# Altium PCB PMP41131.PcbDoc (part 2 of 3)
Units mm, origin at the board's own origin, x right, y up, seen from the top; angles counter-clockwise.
Board outline 53.98 x 39 mm, 6 copper layers (Top Layer, Signal Layer 1, Signal Layer 2, Signal Layer 3, Signal Layer 4, Bottom Layer), stack 1.835 mm thick; 91 components, 60 nets, 285 pads, 252 vias.
Unrouted connection lines stored in the file: 18.
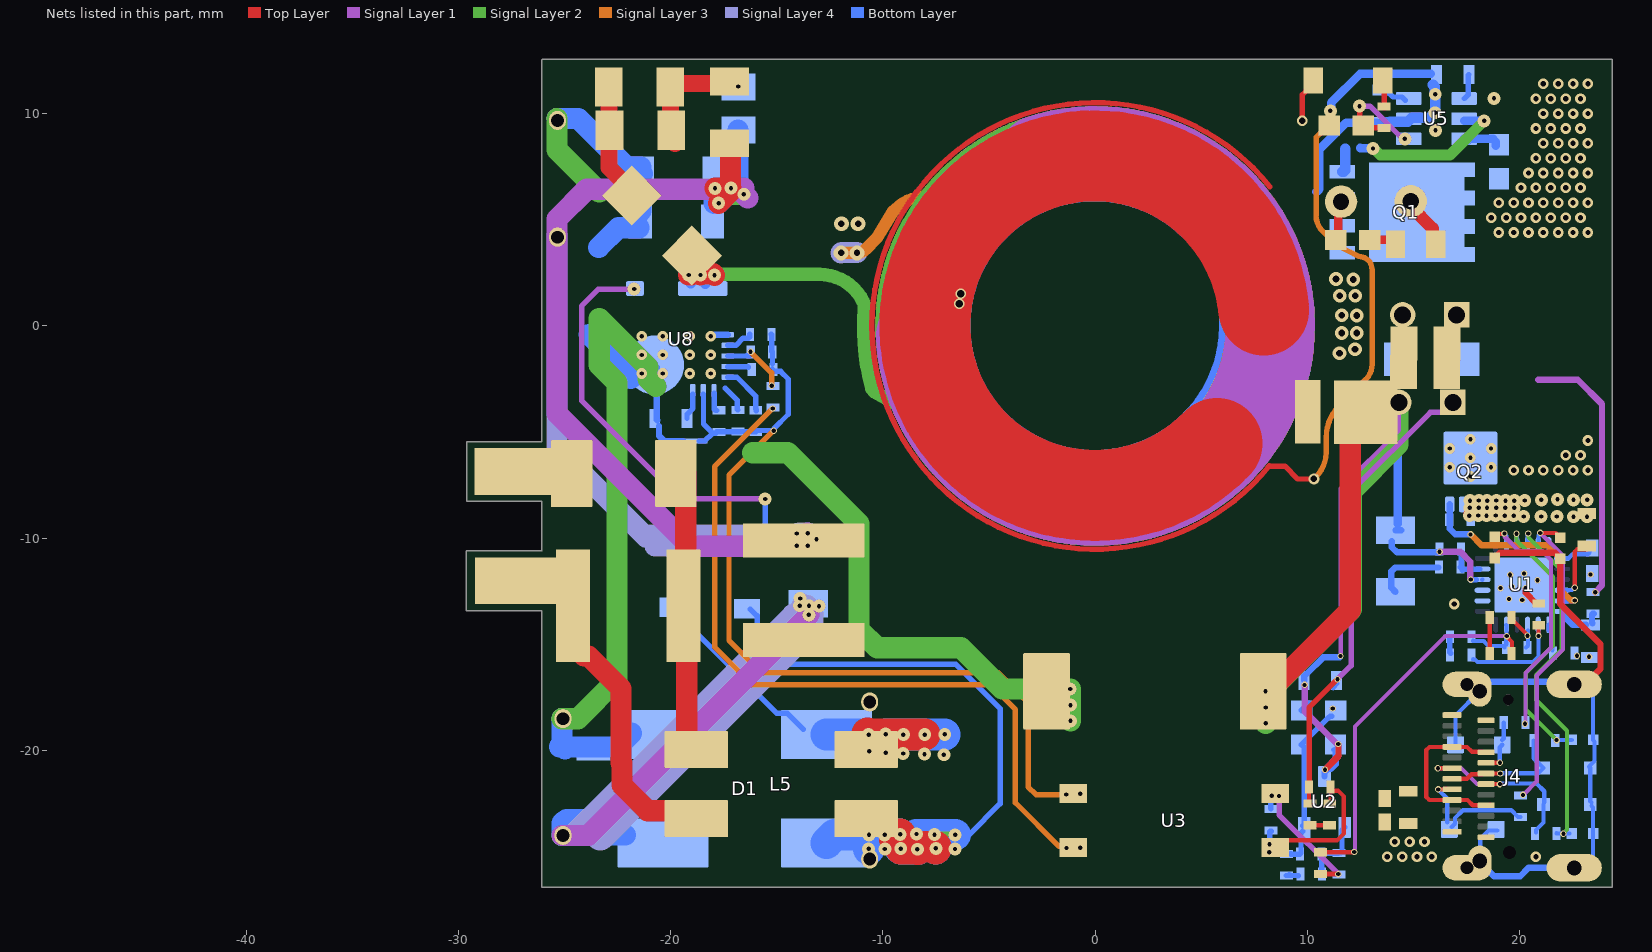
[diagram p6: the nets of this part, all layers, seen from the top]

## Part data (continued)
F1: library part CMP-0124957-1, "50A SMD Fuse 4A 250V 250V SMD Disposable fuses ROHS", Fuse Current=4A, Manufacturer="Shenzhen JDT Fuse", Operating Temperature Range="-55°C to +125°C"
J4: library part CMP-0085712-2, "Receptacle, USB 3.1 Type C, R/A, Gold, SMT", Color=Black, Current_A=1.25A, Manufacturer="JAE Electronics", Voltage_V=20V
L1: library part CMP-0060059-2, "Inductor, Wirewound, Ferrite, 68 uH, 0.9 A, 0.33 ohm, SMD", Manufacturer="Mag Layers", Value1="0.33 ohm", Value2=0.9A, ValueDisplayed=68uH
L5: library part CMP-0124709-1, "Wire Wound Common Mode Choke 1000Ohm @ 100MHz, 4A IDC, 9.0x7.0x4.8mm SMT", Impedance At Frequency="1000Ω @ 100MHz", Manufacturer=MAG-AGA, Operating Temperature Range=to
NT1: library part CMP-0078142-6, "Single point connection between nets.", Manufacturer=N/A
Q1: library part CMP-0001046-2, "MOSFET, N-CH, 150 V, 87 A, PG-TDSON-8", Alternate Manufacturer=None, Manufacturer="Infineon Technologies", Supplier Part Number 1=BSC093N15NS5ATMA1CT-ND, Value2="33 nC"
Q2: library part CMP-0000587-1, "MOSFET, N-CH, 30 V, 60 A, DQG0008A (VSON-CLIP-8)", Alternate Manufacturer=None, Manufacturer="Texas Instruments", Supplier Part Number 1=296-39994-1-ND, Value1=0.003, Value2="23 nC"
R1: library part CMP-0020554-3, "RES, 470 k, 5%, 0.125 W, AEC-Q200 Grade 0, 0805", Manufacturer=Vishay-Dale, Power_W=125mW, Supplier Part Number 1=541-470KACT-ND, TempCo="200 ppm/C", Tolerance_%=5%, Value2=0.125W, Value_Code=470k
R2 R4 R12: library part CMP-0026133-1, "RES, 1.10, 1%, 0.063 W, 0402", Manufacturer=Vishay-Dale, Power_W=63mW, Supplier Part Number 1=541-1.10LLCT-ND, TempCo="100 ppm/C", Tolerance_%=1%, Value2=0.063W, Value_Code=1R10, ValueDisplayed=1.10
R3 R17: library part CMP-0018196-2, "RES, 30.0, 1%, 0.25 W, 1206", Manufacturer="Yageo America", Power_W=250mW, Supplier Part Number 1=311-30.0FRCT-ND, TempCo="100 ppm/C", Tolerance_%=1%, Value2=0.25W, Value_Code=30R0, ValueDisplayed=30.0
R5: library part CMP-0018689-2, "RES, 4.7 k, 5%, 0.25 W, 1206", Manufacturer=Vishay-Dale, Power_W=250mW, Supplier Part Number 1=541-4.7KECT-ND, TempCo="200 ppm/C", Tolerance_%=5%, Value2=0.25W, Value_Code=4k70, ValueDisplayed=4.7k
R7: library part CMP-0026556-2, "RES, 7.68 k, 1%, 0.063 W, AEC-Q200 Grade 0, 0402", Manufacturer=Vishay-Dale, Power_W=63mW, Supplier Part Number 1=541-7.68KLCT-ND, TempCo="100 ppm/C", Tolerance_%=1%, Value2=0.063W, Value_Code=7k68, ValueDisplayed=7.68k
R8: library part CMP-0026220-2, "RES, 28.7 k, 1%, 0.063 W, AEC-Q200 Grade 0, 0402", Manufacturer=Vishay-Dale, Power_W=63mW, Supplier Part Number 1=541-28.7KLCT-ND, TempCo="100 ppm/C", Tolerance_%=1%, Value2=0.063W, Value_Code=28k7, ValueDisplayed=28.7k
R9: library part CMP-0026898-1, "RES, 2.2, 5%, 0.063 W, 0402", Manufacturer=Vishay-Dale, Power_W=63mW, Supplier Part Number 1=541-2.2JCT-ND, TempCo="200 ppm/C", Tolerance_%=5%, Value2=0.063W, Value_Code=2R20, ValueDisplayed=2.2
R10: library part CMP-0026329-2, "RES, 3.01 k, 1%, 0.063 W, AEC-Q200 Grade 0, 0402", Manufacturer=Vishay-Dale, Power_W=63mW, Supplier Part Number 1=541-3.01KLCT-ND, TempCo="100 ppm/C", Tolerance_%=1%, Value2=0.063W, Value_Code=3k01, ValueDisplayed=3.01k
R11: library part CMP-0023550-2, "RES, 43.0 k, 0.1%, 0.1 W, 0603", Manufacturer="Susumu Co Ltd", Power_W=100mW, Supplier Part Number 1=RG16P43.0KBCT-ND, TempCo="25 ppm/C", Tolerance_%=0.1%, Value2=0.1W, Value_Code=43k0, ValueDisplayed=43.0k
R13: library part CMP-0026022-3, "RES, 150, 1%, 0.063 W, AEC-Q200 Grade 0, 0402", Manufacturer=Vishay-Dale, Power_W=63mW, Supplier Part Number 1=541-150LCT-ND, TempCo="100 ppm/C", Tolerance_%=1%, Value2=0.063W, Value_Code=150R, ValueDisplayed=150
R14: library part CMP-0026027-3, "RES, 15.0 k, 1%, 0.063 W, AEC-Q200 Grade 0, 0402", Manufacturer=Vishay-Dale, Power_W=63mW, Supplier Part Number 1=541-15.0KLCT-ND, TempCo="100 ppm/C", Tolerance_%=1%, Value2=0.063W, Value_Code=15k0, ValueDisplayed=15.0k
R15: library part CMP-0026739-1, "RES, 4.70 k, 1%, 0.0625 W, 0402", Manufacturer="Yageo America", Power_W=62.5mW, Supplier Part Number 1=311-4.7KLRCT-ND, TempCo="100 ppm/C", Tolerance_%=1%, Value2=0.0625W, Value_Code=4k70, ValueDisplayed=4.70k
R18: library part CMP-0026866-2, "RES, 1.0, 5%, 0.063 W, 0402", Manufacturer=Vishay-Dale, Power_W=63mW, Supplier Part Number 1=541-1.0JCT-ND, TempCo="200 ppm/C", Tolerance_%=5%, Value2=0.063W, Value_Code=1R00, ValueDisplayed=1.0
R19: library part CMP-0023520-3, "RES, 33.0 k, 0.1%, 0.1 W, 0603", Manufacturer="Susumu Co Ltd", Power_W=100mW, Supplier Part Number 1=RG16P33.0KBCT-ND, TempCo="25 ppm/C", Tolerance_%=0.1%, Value2=0.1W, Value_Code=33k0, ValueDisplayed=33.0k
R21: library part CMP-0026725-1, "RES, 1.00 k, 1%, 0.0625 W, 0402", Manufacturer="Yageo America", Power_W=62.5mW, Supplier Part Number 1=311-1.00KLRCT-ND, TempCo="100 ppm/C", Tolerance_%=1%, Value2=0.0625W, Value_Code=1k00, ValueDisplayed=1.00k
R22: library part CMP-0078497-1, "RES, 0.005, 1%, 1 W, 1206", Manufacturer=Riedon, Power_W=1W, Supplier Part Number 1=696-1372-1-ND, TempCo="50 ppm/C", Tolerance_%=1%, Value_Code=5L000, ValueDisplayed=0.005
R23 R29: library part CMP-0026695-1, "RES, 3.30 k, 1%, 0.1 W, AEC-Q200 Grade 0, 0402", Manufacturer=Panasonic, Power_W=100mW, Supplier Part Number 1=P3.30KLCT-ND, TempCo="100 ppm/C", Tolerance_%=1%, Value2=0.1W, Value_Code=3k30, ValueDisplayed=3.30k
R24 R25 R27 R28: library part CMP-0026970-1, "RES, 6.8, 5%, 0.063 W, 0402", Manufacturer=Vishay-Dale, Power_W=63mW, Supplier Part Number 1=541-6.8JCT-ND, TempCo="200 ppm/C", Tolerance_%=5%, Value2=0.063W, Value_Code=6R80, ValueDisplayed=6.8
R26: library part CMP-0026945-1, "RES, 51 k, 5%, 0.063 W, 0402", Manufacturer=Vishay-Dale, Power_W=63mW, Supplier Part Number 1=541-51KJCT-ND, TempCo="200 ppm/C", Tolerance_%=5%, Value2=0.063W, Value_Code=51k0, ValueDisplayed=51k
R30: library part CMP-0026716-1, "RES, 1.00 k, 1%, 0.063 W, 0402", Manufacturer=Rohm, Power_W=63mW, Supplier Part Number 1=RHM1.00KLCT-ND, TempCo="100 ppm/C", Tolerance_%=1%, Value2=0.063W, Value_Code=1k00, ValueDisplayed=1.00k
R32: library part CMP-0023013-5, "RES, 300, 1%, 0.1 W, 0603", Manufacturer=Yageo, Power_W=100mW, Supplier Part Number 1=311-300HRCT-ND, TempCo="100 ppm/C", Tolerance_%=1%, Value2=0.1W, Value_Code=300R, ValueDisplayed=300
R34: library part CMP-0022438-1, "RES, 47.0 k, 1%, 0.1 W, AEC-Q200 Grade 0, 0603", Manufacturer=Vishay-Dale, Power_W=100mW, Supplier Part Number 1=541-47.0KHCT-ND, TempCo="100 ppm/C", Tolerance_%=1%, Value2=0.1W, Value_Code=47k0, ValueDisplayed=47.0k
R35: library part CMP-0026721-1, "RES, 100 k, 1%, 0.0625 W, 0402", Manufacturer="Yageo America", Power_W=62.5mW, Supplier Part Number 1=311-100KLRCT-ND, TempCo="100 ppm/C", Tolerance_%=1%, Value2=0.0625W, Value_Code=100k
R36: library part CMP-0084244-1, "RES, 1.0 k, 5%, 0.25 W, AEC-Q200 Grade 0, 0603", Manufacturer=Rohm, Power_W=250mW, TempCo="200 ppm/C", Tolerance_%=5%, Value2=0.25W, Value_Code=1k00, ValueDisplayed=1.0k
R42: library part CMP-0025977-1, "RES, 11.5 k, 1%, 0.063 W, 0402", Manufacturer=Vishay-Dale, Power_W=63mW, Supplier Part Number 1=541-11.5KLCT-ND, TempCo="100 ppm/C", Tolerance_%=1%, Value2=0.063W, Value_Code=11k5, ValueDisplayed=11.5k
R43: library part CMP-0026464-2, "RES, 5.23 k, 1%, 0.063 W, AEC-Q200 Grade 0, 0402", Manufacturer=Vishay-Dale, Power_W=63mW, Supplier Part Number 1=541-5.23KLCT-ND, TempCo="100 ppm/C", Tolerance_%=1%, Value2=0.063W, Value_Code=5k23, ValueDisplayed=5.23k
R50: library part CMP-0025712-2, "RES, 12, 5%, 0.1 W, 0603", Manufacturer=Vishay-Dale, Power_W=100mW, Supplier Part Number 1=541-12GCT-ND, TempCo="200 ppm/C", Tolerance_%=5%, Value2=0.1W, Value_Code=12R0, ValueDisplayed=12
RT1: library part CMP-0002353-2, "Thermistor NTC, 100k ohm, 1%, 0402", Manufacturer=MuRata, Power_W=100mW, Tolerance_%=1%
U1: library part CMP-0124680-1, "Integrate multiple protocols, fast charging protocol IC for USBC port", Manufacturer=Injoinic, Max Supply Voltage=25V, Min Supply Voltage=3V, Operating Temperature Range="-40°C to +85°C", Part Number=IP2723TH
U2: library part CMP-0066199-1, "2.5V Low Iq Adjustable Precision Shunt Regulator, DBZ0003A (SOT-23-3)", Alternate Manufacturer="Texas Instruments"
U3: library part CMP-0006160-3, "Optocoupler, 5 kV, 63-125% CTR, SMT", Manufacturer=Vishay-Semiconductor, Supplier Part Number 1=VOL618A-2TCT-ND, Voltage_Isolation_Vrms=5kV
U5: library part CMP-0086802-1, "FAST TURN-OFF INTELLIGENT RECTIF", Manufacturer="Monolithic Power Systems"
U8: library part CMP-0121635-2, Manufacturer="Texas Instruments", Operating Temperature Range=to, PartNumber=UCG28826

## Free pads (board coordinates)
  rect 4x2.2 smd: 5(-27.23,-6.86) 5(-27.22,-12.01)
  rect 1.2x3 smd: 9(10.01,-4.04)
  rect 3x3 smd: 9(12.74,-4.07)
  round 1.524 hole 0.762: 10(11.58,5.85) 10(14.86,5.87)

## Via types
v1: diameter 0.61, hole 0.203, Top Layer to Bottom Layer, tented both sides, 89 vias
v2: diameter 0.5, hole 0.25, Top Layer to Bottom Layer, 75 vias
v3: diameter 0.3, hole 0.2, Top Layer to Bottom Layer, tented both sides, 49 vias
v4: diameter 0.5, hole 0.2, Top Layer to Bottom Layer, tented both sides, 13 vias
v5: diameter 0.65, hole 0.32, Top Layer to Bottom Layer, 10 vias
v6: diameter 0.5, hole 0.2, Top Layer to Bottom Layer, 6 vias
v7: diameter 0.508, hole 0.305, Top Layer to Bottom Layer, 4 vias
v8: diameter 0.7, hole 0.3, Signal Layer 1 to Signal Layer 4, tented both sides, 4 vias
v9: diameter 0.5, hole 0.35, Signal Layer 2 to Signal Layer 3, tented both sides, 2 vias

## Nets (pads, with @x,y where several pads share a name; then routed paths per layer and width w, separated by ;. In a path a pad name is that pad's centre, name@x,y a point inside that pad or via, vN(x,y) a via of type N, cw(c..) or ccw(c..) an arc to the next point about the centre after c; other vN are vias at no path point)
APGND: C16.2 NT1.2 R7.1 R8.1 R42.1 R43.1 RT1.1 U3.3 U8.10 | length 43.3
  Signal Layer 3 w0.254: v3@-15.162,-4.94 -15.178,-4.956 -15.186,-4.956 -17.25,-7.02 -17.25,-14.82 -15.731,-16.339 -4.561,-16.339 -3.16,-17.74 -3.16,-21.71 -2.79,-22.08 -1.38,-22.08 -1.355,-22.055 -0.725,-22.055 v1(-0.71,-22.04)
  Bottom Layer w0.254: NT1.2@-18.648,-5.42 -18.394,-5.42 -18.036,-5.062 R7.1@-17.872,-5.062 ; U8.10@-18.458,-3.213 -18.458,-3.261 -18.45,-3.269 -18.45,-4.62 -18.06,-5.01 ; R7.1@-17.83,-4.998 -17.825,-4.993 R42.1@-16.037,-4.993 ; R42.1@-15.99,-4.988 -15.927,-4.924 -15.134,-4.924 v3(-15.142,-4.933) ; RT1.1@-15.252,-0.4 -15.232,-0.42 -15.232,-1.2 C16.2@-15.212,-1.22 ; R43.1@-15.222,-2.03 -15.222,-2.079 -15.159,-2.142 -14.818,-2.142 -14.46,-2.5 -14.46,-4.16 -15.133,-4.833 v3@-15.133,-4.924 ; R43.1@-15.2,-1.79 C16.2@-15.2,-1.232
  other v1: -1.37,-22.07
CC1: D6.2 J4.A5 R25.2 | length 6
  Top Layer w0.2: v3(16.15,-21.83) 16.49,-21.83 J4.A5@16.52,-21.8
  Bottom Layer w0.2: v3(16.15,-21.83) 16.58,-22.26 D6.2@16.58,-23.38 ; D6.2@16.79,-23.6 16.947,-23.443 16.947,-23.183 17.32,-22.81 19.598,-22.81 19.916,-23.128 R25.2@20.03,-23.128
CC2: D8.2 J4.B5 R28.2 | length 2.2
  Top Layer w0.2: J4.B5@18.6,-20.55 18.63,-20.58 v3(19.06,-20.58)
  Bottom Layer w0.2: v3@19.05,-20.57 19.05,-19.85 D8.2@19.17,-19.73 ; D8.2@19.16,-19.51 D8.2@19.195,-19.475 ; D8.2@19.19,-19.47 19.202,-19.47 19.242,-19.43 R28.2@19.242,-18.69
DN: D2.2 J4.A7 J4.B7 R24.2 | length 8.8
  Top Layer w0.2: v3(16.14,-20.84) 16.145,-20.835 16.805,-20.835 J4.A7@16.81,-20.83 ; J4.B7@18.41,-21.58 v3(19.06,-21.58)
  Signal Layer 1 w0.2: v3(16.14,-20.84) 16.15,-20.83 17.23,-20.83 17.98,-21.58 v3(19.06,-21.58)
  Bottom Layer w0.2: v3(19.06,-21.58) 19.079,-21.561 19.15,-21.561 19.161,-21.55 20.78,-21.55 21.15,-21.92 D2.2@21.15,-22.44 ; R24.2@20.76,-23.86 20.76,-23.738 21.11,-23.388 D2.2@21.11,-22.54
DN1: C28.2 R24.1 U1.16 | length 17.1
  Signal Layer 2 w0.2: v3(20.39,-9.78) 20.409,-9.799 20.409,-9.959 20.86,-10.41 21.97,-11.52 21.97,-15.25 20.77,-16.45 20.77,-17.62 22.22,-19.07 22.22,-23.723 22.05,-23.893 v3(22.05,-23.92)
  Bottom Layer w0.2: U1.16@20.364,-10.324 20.372,-10.317 20.372,-9.798 v3(20.39,-9.78) ; R24.1@21.728,-23.9 21.738,-23.91 C28.2@22.34,-23.91
DP: D7.2 J4.A6 J4.B6 R27.2 | length 5.8
  Top Layer w0.2: J4.A6@16.81,-21.33 17.51,-21.33 17.725,-21.115 18.195,-21.115 J4.B6@18.22,-21.09 ; J4.B6@18.41,-21.08 v3(19.07,-21.08)
  Bottom Layer w0.2: v3@19.08,-21.07 20.86,-21.07 D7.2@21.11,-20.82 20.652,-20.362 R27.2@20.652,-19.53
DP1: C29.2 R27.1 U1.15 | length 12.9
  Signal Layer 2 w0.2: v3(19.84,-9.79) 19.84,-10.1 21.55,-11.81 21.55,-15.08 20.28,-16.35 20.28,-18.06 v3(21.73,-19.51)
  Bottom Layer w0.2: v3(19.84,-9.79) 19.857,-9.807 19.857,-10.317 U1.15@19.864,-10.324 ; R27.1@21.668,-19.53 21.698,-19.5 R27.1@21.72,-19.5 ; v3(21.73,-19.51) R27.1@21.72,-19.5 ; C29.2@22.44,-19.5 R27.1@21.72,-19.5
FB_ACDC: C12.1 C14.2 C23.2 R18.1 U1.5 | length 19.8
  Top Layer w0.2: R18.1@10.6,-24.792 10.606,-24.786 12.194,-24.786 v3(12.2,-24.78) ; v3(19.38,-14.61) 19.38,-14.637 19.63,-14.887 19.63,-15.28 C23.2@19.62,-15.29
  Signal Layer 1 w0.2: v3(12.2,-24.78) 12.219,-24.761 12.219,-24.69 12.23,-24.679 12.23,-18.87 16.49,-14.61 v3(19.38,-14.61)
  Bottom Layer w0.2: C14.2@17.79,-14.826 17.808,-14.845 18.295,-14.845 18.53,-15.08 19.202,-15.08 C12.1@19.272,-15.15 ; C12.1@19.33,-15.03 19.361,-14.999 19.361,-14.629 v3(19.38,-14.61) 19.372,-14.602 19.372,-14.092 U1.5@19.362,-14.082
HVC: C5.1 R4.2 U5.1 | length 4.8
  Top Layer w0.254: v1(12.45,10.35) 12.45,9.52 12.64,9.33 R4.2@13.602,9.33
  Signal Layer 1 w0.254: v1(12.45,10.35) 12.94,10.35 14.412,8.878 14.512,8.878 v1(14.58,8.81)
LINE: F1.1 pad.5@-27.23,-6.86 | length 2.8
  Top Layer w1: pad.5@-27.23,-6.86 -24.76,-6.87 F1.1@-24.63,-6.74 ; F1.1@-24.54,-6.71 F1.1@-24.44,-6.81
NetC1_1: C1.1 F1.2 L5.1 | length 13.6
  Top Layer w1: F1.2@-19.44,-6.81 -19.29,-6.96 C1.1@-19.29,-13.09 ; C1.1@-19.39,-13.19 -19.235,-13.345 -19.235,-19.904 -18.842,-19.904 L5.1@-18.79,-19.956
NetC2_1: C2.1 C8.1 D1.1 L1.1 R5.1 | length 51.2
  Signal Layer 1 w1: C8.1@-25.12,-24 -23.88,-24 v1(-13.49,-13.61)
  Signal Layer 4 w1: -23.31,-24 -24.65,-24 -14.26,-13.61 v1@-13.62,-13.61
  Signal Layer 4 w1.4: -23.31,-24 -13.49,-14.18 v1(-13.49,-13.61) -13.62,-13.61 -13.62,-13.404 v1@-13.67,-13.354
  Bottom Layer w1: C8.1@-25.12,-24 -25.12,-23.42 -25.05,-23.35 ; -24.91,-23.25 -23.88,-23.25 -23.15,-23.98 D1.1@-22.14,-23.98
  other v1: -13.01,-13.2 -13.92,-13.18 -13.48,-13.18 -13.9,-12.84
NetC3_1: C3.1 R1.1 R3.2 R17.2 | length 5.1
  Top Layer w0.8: R3.2@-19.97,9.28 -20.01,9.32 -20.01,11.11 -20.02,11.12 -20.02,11.17 -19.77,11.42 -17.18,11.42 C3.1@-17.1,11.5 ; R3.2@-19.79,8.59 R3.2@-19.79,8.75
  other v1: -16.81,11.28
NetC7_1: C7.1 D1.3 D4.2 L5.2 | length 16.5
  Top Layer w1.5: L5.2@-9.87,-19.355 L5.2@-9.773,-19.258 ; v1(-8.03,-19.25) -8.98,-19.25 -9.01,-19.28 v1(-9.04,-19.25) -9.06,-19.23 v1(-9.87,-19.23) -10.65,-19.23 v1(-10.67,-19.25) ; v1(-10.67,-19.25) -10.73,-19.19 v1(-10.67,-19.25)
  Bottom Layer w0.254: D4.2@-19.92,-13.257 -19.767,-13.257 -19.437,-13.588 -19.437,-13.813 -15.013,-18.237 -14.513,-18.237 D1.3@-13.75,-19
  Bottom Layer w1.5: D1.3@-12.66,-19.25 v1(-10.67,-19.25) ; v1(-9.87,-19.23) -9.85,-19.25 v1(-9.04,-19.25) -7.83,-19.25 -7.82,-19.24 v1(-7.09,-19.24)
  other v1: -7.13,-20.2 -8.04,-20.17 -9.05,-20.14 -9.87,-20.11 -10.64,-20.04
NetC7_2: C7.2 D1.2 D5.2 L5.4 | length 34.4
  Top Layer w1.5: -9.435,-24.195 v1(-9.19,-23.95) ; v1(-9.16,-24.62) -9.15,-24.61 v1@-8.38,-24.61 ; v1@-8.42,-24.61 -8.42,-24.53 -7.51,-24.53 v1(-7.51,-24.61) ; v1@-8.42,-24.61 v1(-8.38,-24.65)
  Signal Layer 2 w0.254: v1(-9.19,-23.95) v1@-6.6,-23.95
  Bottom Layer w0.254: D5.2@-16.247,-13.347 -16.237,-13.347 -15.927,-13.658 -15.927,-13.797 -15.917,-13.807 -15.917,-14.353 -14.33,-15.94 -6.56,-15.94 -4.48,-18.02 -4.48,-22.5 -5.95,-23.97 v1(-6.6,-23.97)
  Bottom Layer w1.5: D1.2@-12.66,-24.35 -12.28,-23.97 -10.67,-23.97 v1(-10.66,-23.97) ; v1(-10.67,-24.63) -10.66,-24.62 v1(-10.66,-23.97) ; v1@-9.81,-23.97 v1(-9.92,-23.97) v1(-10.66,-23.97) ; v1(-9.19,-23.95) -9.19,-24.59 v1(-9.16,-24.62) v1@-8.41,-24.62 ; v1(-8.38,-24.65) v1@-8.41,-24.62 ; v1(-7.51,-24.61) -7.51,-24.03 v1@-7.57,-23.97 ; v1(-6.6,-23.97) v1@-7.57,-23.97 ; v1@-8.41,-24.62 -8.42,-24.61 -8.42,-23.97 v1@-7.57,-23.97
  other v1: -9.91,-24.64 -6.61,-24.64 -7.57,-23.96 -8.42,-23.93
NetC10_1: C10.1 R9.2 U1.24 | length 1.9
  Bottom Layer w0.3: U1.24@22.175,-13.48 22.175,-13.775 22.48,-14.08 C10.1@23.113,-14.08 ; C10.1@23.42,-14.01 23.4,-13.99 23.4,-13.598 R9.2@23.44,-13.558 R9.2@23.48,-13.558
NetC11_1: C11.1 U1.1 | length 1.3
  Bottom Layer w0.2: U1.1@21.364,-14.076 21.364,-14.336 21.384,-14.356 21.423,-14.356 21.54,-14.473 C11.1@21.54,-15.278
NetC12_2: C12.2 R29.2 U1.3 | length 1.7
  Top Layer w0.2: R29.2@19.65,-13.85 v3@20.34,-14.54
  Bottom Layer w0.2: C12.2@20.288,-15.15 20.378,-15.06 20.378,-14.672 v3@20.39,-14.66 ; v3@20.379,-14.571 U1.3@20.379,-14.351
  other v3: 20.36,-14.59
NetC13_1: C13.1 R50.2 | length 1
  Top Layer w0.4: R50.2@12.93,4.05 13.92,4.05 C13.1@13.95,4.02
NetC14_1: C14.1 R23.1 | length 0.8
  Bottom Layer w0.254: C14.1@16.702,-14.64 16.702,-15.382 R23.1@16.74,-15.42
NetC15_1: C15.1 U8.11 | length 1.3
  Bottom Layer w0.254: C15.1@-19.228,-4.36 -19.228,-4.169 -18.95,-3.891 -18.95,-3.221 U8.11@-18.958,-3.213
NetC16_1: C16.1 R12.1 U8.5 | length 3.2
  Signal Layer 3 w0.254: v3(-16.232,-1.223) -15.24,-2.215 v3@-15.24,-2.79
  Bottom Layer w0.254: U8.5@-17.31,-1.415 -16.44,-1.415 -16.423,-1.398 -16.292,-1.398 -16.228,-1.334 C16.1@-16.228,-1.22
  other v3: -15.242,-2.823
NetC18_2: C18.2 R13.2 | length 0.8
  Top Layer w0.2: C18.2@10.24,-23.58 10.302,-23.518 R13.2@11.03,-23.518
NetC20_1: C20.1 R15.1 | length 0.6
  Bottom Layer w0.254: R15.1@9,-25.888 9.548,-25.888 C20.1@9.56,-25.9 ; R15.1@9.14,-25.84 R15.1@9.144,-25.844
NetC20_2: C20.2 C21.2 R2.1 U2.1 | length 3.1
  Bottom Layer w0.254: C21.2@10.658,-24.87 10.682,-24.846 R2.1@11.454,-24.846 ; C21.2@10.67,-24.918 10.67,-25.742 C20.2@10.728,-25.8 ; R2.1@11.48,-24.822 11.556,-24.822 11.62,-24.759 11.62,-23.75 U2.1@11.75,-23.62
NetC21_1: C21.1 R11.1 R15.2 R19.2 U2.2 | length 7.5
  Bottom Layer w0.254: R15.2@9.2,-24.86 9.23,-24.89 C21.1@9.642,-24.89 ; C21.1@9.642,-24.87 9.69,-24.822 9.69,-23.89 U2.2@9.78,-23.8 ; U2.2@9.78,-23.54 9.85,-23.47 9.85,-19.86 R19.2@9.71,-19.72 10.979,-18.451 cw(c11.15,-18.621) R11.1@11.15,-18.38
  other v3: 11.19,-18.02
NetC23_1: C23.1 R29.1 | length 1.6
  Top Layer w0.2: C23.1@18.582,-15.42 18.582,-13.878 R29.1@18.64,-13.82
NetC24_2: 
NetC26_1: C26.1 R21.1 U1.11 | length 1.4
  Bottom Layer w0.254: R21.1@17.198,-11.36 17.24,-11.318 C26.1@17.24,-10.777 ; R21.1@17.286,-11.516 17.341,-11.46 U1.11@18.11,-11.46
NetC31_1: C31.1 U5.4 | length 1.2
  Bottom Layer w0.254: U5.4@17.37,10.71 17.387,10.71 17.56,10.883 17.56,11.8 C31.1@17.6,11.84
NetD3_1: D3.1 R3.1 R17.1 | length 5.4
  Top Layer w0.8: R17.1@-22.91,11.11 -22.91,9.415 -22.9,9.405 -22.9,7.456 -21.828,6.384 D3.1@-21.828,6.138
NetD4_1: D4.1 D5.1 U8.1 | length 23
  Signal Layer 1 w0.254: v1@-21.7,1.73 -23.4,1.73 -24.19,0.94 -24.19,-3.52 -19.56,-8.15 v1(-15.55,-8.15)
  Bottom Layer w0.254: D4.1@-19.54,-9.912 -16.118,-9.912 D5.1@-16.11,-9.92 ; D5.1@-15.928,-9.72 -15.55,-9.342 v1(-15.55,-8.15)
  other v1: -21.72,1.74
NetD9_1: D9.1 R4.1 | length 1.3
  Top Layer w0.254: D9.1@13.537,11.55 13.62,11.467 R4.1@13.62,10.27
NetQ1_4: Q1.4 U5.5 | length 8.7
  Signal Layer 2 w0.5: v1@13.131,8.339 13.42,8.05 16.71,8.05 v1(18.32,9.66)
  Bottom Layer w0.4: 12.47,8.39 12.49,8.37 13.07,8.37 v1(13.08,8.36) ; U5.5@17.37,9.66 18.26,9.66 v1@18.27,9.67
  Bottom Layer w0.5: Q1.4@11.64,7.26 11.705,7.26 11.78,7.335 11.78,8.33
NetQ2_4: Q2.4 R35.1 U1.23 | length 9.9
  Signal Layer 3 w0.3: v3(17.68,-9.82) 18.19,-10.33 21.29,-10.33 21.92,-10.96 21.92,-12.45 22.39,-12.92 v3@22.59,-12.92
  Bottom Layer w0.254: U1.23@21.99,-12.95 21.997,-12.943 22.565,-12.943 22.59,-12.918 v3@22.59,-12.91
  Bottom Layer w0.3: Q2.4@16.695,-8.403 16.695,-9.555 16.96,-9.82 v3@17.665,-9.82
  other v3: 22.59,-12.93
NetR2_2: R2.2 R14.1 R18.2 U3.2 | length 6.9
  Top Layer w0.254: R18.2@10.64,-25.82 10.646,-25.814 11.444,-25.814 v3(11.45,-25.82)
  Signal Layer 1 w0.254: v3(8.31,-22.13) v3@8.62,-22.13 ; v3(8.66,-22.14) 8.66,-23.03 v3(11.45,-25.82)
  Bottom Layer w0.254: v3@8.26,-22.2 8.26,-22.732 R14.1@8.28,-22.752 ; v3(8.31,-22.13) 8.319,-22.121 8.679,-22.121 v3@8.69,-22.11
NetR7_2: R7.2 U8.9 | length 0.9
  Bottom Layer w0.254: U8.9@-17.95,-3.18 -17.95,-3.919 -17.887,-3.982 R7.2@-17.83,-3.982
NetR8_2: R8.2 U8.8 | length 1.3
  Bottom Layer w0.254: U8.8@-17.423,-2.937 -16.87,-3.49 -16.87,-3.922 R8.2@-16.83,-3.962
NetR10_1: R10.1 R13.1 R14.2 U3.1 | length 7.6
  Top Layer w0.2: U3.1@8.73,-24.41 8.91,-24.23 11.39,-24.23 11.71,-23.91 11.71,-22.17 11.429,-21.889 11.168,-21.889 11.078,-21.798 R10.1@11.078,-21.72 R10.1@11.078,-21.832 ; R13.1@11.03,-22.502 11.078,-22.454 R10.1@11.078,-21.834
  Bottom Layer w0.2: v3(8.2,-24.79) 8.205,-24.785 8.205,-24.425 v3(8.21,-24.42)
  Bottom Layer w0.254: v3(8.21,-24.42) 8.219,-24.411 8.219,-23.831 8.24,-23.81 R14.2@8.3,-23.81
NetR12_2: R12.2 U3.4 | length 36.1
  Signal Layer 3 w0.254: v3(-15.192,-3.893) -17.93,-6.631 -17.93,-15.13 -16.152,-16.908 -4.922,-16.908 -3.76,-18.07 -3.76,-22.46 -1.698,-24.522 -1.418,-24.522 v1(-1.35,-24.59) -1.345,-24.585 -0.705,-24.585 v1(-0.7,-24.58)
NetR23_2: R23.2 R30.2 U1.2 | length 5.2
  Top Layer w0.2: v3@20.89,-14.6 20.88,-14.59 20.88,-14.108 R30.2@20.89,-14.098
  Bottom Layer w0.2: R23.2@17.8,-15.706 17.808,-15.715 17.885,-15.715 18,-15.83 20.63,-15.83 20.88,-15.58 v3(20.88,-14.6) 20.872,-14.592 20.872,-14.089 U1.2@20.867,-14.084
NetR26_2: R26.2 U1.19 | length 1.5
  Bottom Layer w0.2: U1.19@21.99,-10.95 21.998,-10.942 22.298,-10.942 22.49,-10.75 23.21,-10.75 23.28,-10.68 R26.2@23.28,-10.54
NetR32_2: R32.2 U5.6 | length 1.7
  Bottom Layer w0.4: U5.6@17.37,8.81 18.735,8.81 18.86,8.685 R32.2@18.86,8.49 ; U5.6@17.54,8.71 U5.6@17.545,8.715
NetR34_2: R34.2 U5.3 | length 1.3
  Bottom Layer w0.254: R34.2@13.51,11.112 13.701,11.112 14.029,10.783 14.447,10.783 U5.3@14.6,10.63
NetR36_1: R36.1 U1.22 | length 3
  Top Layer w0.2: v3(22.59,-12.33) 22.59,-10.633 22.707,-10.516 23.174,-10.516 R36.1@23.2,-10.49
  Bottom Layer w0.2: U1.22@21.99,-12.45 21.998,-12.442 22.45,-12.442 22.563,-12.33 v3(22.59,-12.33)
NetR42_2: R42.2 U8.7 | length 2.4
  Bottom Layer w0.254: U8.7@-17.31,-2.415 -16.885,-2.415 -16,-3.3 -16,-3.908 -15.96,-3.948 R42.2@-15.96,-3.99
NetR43_2: R43.2 U8.6 | length 1
  Bottom Layer w0.254: U8.6@-17.31,-1.915 -17.308,-1.917 -16.363,-1.917 R43.2@-16.34,-1.94
NetRT1_2: RT1.2 U8.4 | length 1.3
  Bottom Layer w0.254: U8.4@-17.31,-0.915 -17.308,-0.913 -16.923,-0.913 -16.588,-0.578 -16.332,-0.578 -16.268,-0.514 RT1.2@-16.268,-0.4
Neture: C1.2 L5.3 pad.5@-27.22,-12.01 | length 16.2
  Top Layer w1: pad.5@-26.36,-12.03 C1.2@-24.76,-12.03 ; C1.2@-24.72,-12.03 C1.2@-24.42,-12.33 ; C1.2@-24.59,-13.19 -24.59,-15.04 -24.08,-15.55 -23.869,-15.55 -22.333,-17.086 -22.333,-20.59 ; C1.2@-24.37,-13.19 C1.2@-24.37,-12.64 ; -22.29,-20.59 -22.29,-21.629 -21.088,-22.831 -19.165,-22.831 L5.3@-18.79,-23.206
PGND: C2.2 C8.2 C9.2 C15.2 C19.2 C22.2 C32.1 D1.4 NT1.1 U8.3 U8.12 | length 82.9
  Top Layer w0.2: C32.1@-2.294,-17.209 -2.185,-17.1 v1(-1.18,-17.1) ; C32.1@-1.27,-18.5 v1(-1.17,-18.6) C32.1@-1.27,-18.5 ; C32.1@-1.27,-17.96 v1(-1.17,-17.86) C32.1@-1.27,-17.96
  Signal Layer 2 w0.637: -12.986,2.426 cw(c-12.986,0.141) -10.932,1.143 cw(c-11.504,0.864) -10.87,0.809 ccw(c-0.344,-0.097) -10.516,-2.95
  Signal Layer 2 w1: C9.2@-25.35,9.77 -25.35,8.3 -23.36,6.31 ; C8.2@-25.12,-18.5 -24.36,-18.5 -22.52,-16.66 -22.52,-2.68 -23.36,-1.84 -23.36,0.35 -21.063,-1.947 ; -21.063,-2.487 -20.69,-2.86 ; -16.13,-5.97 -14.48,-5.97 -11.13,-9.32 -11.13,-14.3 -10.27,-15.16 -6.32,-15.16 -4.38,-17.1 v1(-1.18,-17.1) ; v1(-1.17,-18.6) v1(-1.17,-17.86) v1@-1.17,-17.11
  Bottom Layer w0.3: U8.12@-20.758,-1.839 -20.655,-1.942 -20.655,-4.425 C15.2@-20.63,-4.45 ; C15.2@-20.55,-4.72 -20.55,-5.17 -20.3,-5.42 NT1.1@-19.41,-5.42 ; v4@-17.94,-0.43 -17.925,-0.415 U8.3@-17.31,-0.415
  Bottom Layer w1: C9.2@-25.35,9.77 -24.35,9.77 -22.05,7.47 C22.2@-21.39,7.47 ; -25.23,-19.82 -25.19,-19.82 -25.12,-19.75 C8.2@-25.12,-18.5 ; -24.98,-19.92 -24.9,-19.84 -22.49,-19.84 D1.4@-21.84,-19.19 ; -23.85,-0.4 -22.414,-1.836 ; -23.39,3.69 -22.46,4.62 C19.2@-21.49,4.62 ; U8.12@-21.873,-2.47 -21.584,-2.181 -21.419,-2.181 v4(-21.36,-2.24) ; U8.12@-21.85,-2.18 U8.12@-21.81,-2.14 ; C19.2@-21.49,5.31 -21.39,5.41 -21.39,7.12 C22.2@-21.34,7.17
  other v4: -20.37,-2.24 -19.1,-2.24 -18.11,-2.24 -21.36,-1.365 -20.37,-1.365 -19.1,-1.365 -18.11,-1.365 -21.36,-0.49 -20.37,-0.49 -19.1,-0.49 -18.11,-0.49
RTN: C27.1 C28.1 C29.1 C30.1 C38.2 D2.1 D6.1 D7.1 D8.1 D13.2 J4.A1 J4.A12 J4.B1 J4.B12 J4.S1 J4.S2 J4.S3 J4.S4 R21.2 R22.2 | length 37.3
  Top Layer w0.3: C30.1@18.72,-11.01 18.74,-11.01 19.06,-10.69 21.664,-10.69 C27.1@21.81,-10.836 ; C27.1@21.9,-10.98 21.9,-13.1 23.8,-15 23.8,-16.15 23.37,-16.58 J4.S4@23.25,-16.58
  Bottom Layer w0.2: D8.1@16.97,-19.73 16.97,-18.35 J4.S2@18.11,-17.21 ; J4.S1@18.13,-25.11 18.13,-24.17 18.53,-23.77 D6.1@18.93,-23.77 ; J4.S4@21.784,-16.51 J4.S4@22.13,-16.51 ; J4.S3@22.82,-25.5 22.937,-25.5 23.45,-24.987 C28.1@23.45,-23.91 23.45,-22.68 D2.1@23.37,-22.6 ; J4.S3@22.86,-25.16 J4.S3@22.91,-25.21 ; J4.S4@22.89,-17.29 23.317,-17.29 23.45,-17.423 C29.1@23.45,-19.5 ; D7.1@23.25,-20.76 23.52,-20.49 C29.1@23.52,-19.59 ; D7.1@23.31,-20.82 23.31,-22.39 D2.1@23.37,-22.45
  Bottom Layer w0.3: R22.2@14.14,-12.53 13.95,-12.34 13.95,-11.556 14.126,-11.38 R21.2@16.162,-11.38 ; J4.S2@17.51,-16.885 18.304,-16.885 18.429,-16.76 22.435,-16.76 J4.S4@22.56,-16.885 ; J4.S1@18.11,-25.25 18.78,-25.92 20.012,-25.92 20.407,-25.525 22.075,-25.525 J4.S3@22.25,-25.7
  other v2: 13.755,-24.999 14.455,-24.999 15.155,-24.999 15.855,-24.999 20.755,-24.999 20.755,-24.999 14.105,-24.299 14.805,-24.299 15.505,-24.299
SGND: C4.2 C6.2 C10.2 C11.2 C17.1 C26.2 C32.2 C49.2 EC6.2 EC7.2 pad.9@12.74,-4.07 R19.1 R22.1 R26.1 R30.1 U1.8 U1.9 U1.10 U1.18 U1.25 U2.3 | length 67
  Top Layer w0.3: v3(10.82,-20.9) 11.46,-20.26 v3@11.46,-19.72 ; v3@20.27,-12.42 20.27,-12.576 20.776,-13.082 R30.1@20.89,-13.082
  Top Layer w1: v1(8.02,-17.21) 8.115,-17.21 8.19,-17.21 12.01,-13.39 pad.9@12.01,-4.69
  Signal Layer 1 w0.2: v3@11.56,-15.56 11.56,-7.66 14.3,-4.92 EC7.2@14.3,-3.6
  Signal Layer 1 w0.3: v3(9.86,-16.91) 9.86,-18.16 v3@11.4,-19.7 ; v3(10.82,-20.9) 11.46,-20.26 v3@11.46,-19.74 ; v3(16.22,-10.64) 17.2,-10.64 17.67,-11.11 v3@17.67,-11.9
  Signal Layer 2 w1: v1@8.01,-17.25 8.02,-17.97 v1(8.03,-18.71) ; v1(8.02,-17.21) 8.2,-17.21 12.06,-13.35 12.06,-7.79 14.262,-5.588 14.262,-3.692 14.344,-3.61 EC7.2@14.37,-3.61
  Bottom Layer w0.2: R19.1@11.215,-19.96 R19.1@11.24,-19.96 ; U1.10@18.231,-11.958 U1.10@18.239,-11.95
  Bottom Layer w0.254: v3(17.69,-11.95) U1.10@17.95,-11.95
  Bottom Layer w0.3: C17.1@9.838,-16.7 9.838,-16.509 9.942,-16.405 10.747,-15.6 v3@11.52,-15.6 ; U2.3@10.8,-21.22 10.8,-21.02 10.95,-20.87 11.095,-20.87 11.32,-20.645 R19.1@11.32,-19.95 ; R22.1@13.97,-10.15 13.97,-10.42 14.21,-10.66 15.996,-10.66 16.001,-10.655 16.205,-10.655 v3(16.22,-10.64) ; R22.1@14.14,-9.63 R22.1@14.415,-9.63
  Bottom Layer w0.4: 14.14,-4.28 14.24,-4.38 R22.1@14.24,-9.32
  other v1: 8.03,-17.97
  other v2: 16.905,-13.099 16.905,-13.099
  other v3: 11.44,-19.69 23.26,-15.58 11.55,-15.55 22.69,-15.53 20.11,-12.91 19.49,-12.86 20.27,-12.36 19.09,-12.35 19.62,-12.28 20.83,-11.98 19.54,-11.72 23.33,-11.71 20.2,-11.66
Vaux: D9.2 | length 1.8
  Top Layer w0.254: v7(9.75,9.66) 9.75,10.885 10.015,11.15 D9.2@10.14,11.15
  Bottom Layer w0.254: v7@9.701,9.611 v7(9.75,9.66)
Vbus: C3.2 C9.1 C19.1 C22.1 L1.2 R1.2 R5.2 | length 677.2
  Top Layer w1: v1(-17.91,6.48) -17.9,6.49 v1(-17.16,6.49) ; v1(-17.74,5.78) -17.16,6.36 v1(-17.16,6.49) ; C3.2@-17.025,8.66 -17.025,8.61 -17.175,8.46 -17.175,6.505 v1(-17.16,6.49)
  Signal Layer 1 w1: C9.1@-25.35,4.208 -25.35,-4.12 -19.41,-10.06 ; C9.1@-25.35,4.27 -25.35,5.04 -23.95,6.44 v1@-17.95,6.44 ; -19.18,-10.38 -14.364,-10.38 -14.344,-10.36 v1(-14.06,-10.36) ; v1(-17.74,5.78) -17.475,6.045 ; v1(-17.16,6.49) v1@-16.55,6.49 ; v1(-16.55,6.2) v1@-16.37,6.02 ; v1@-13.875,-10.175 v1@-13.715,-10.175 ; v1(-13.54,-10.35) v1@-13.715,-10.175 ; v1(-13.54,-9.77) -13.54,-10 v1@-13.715,-10.175
  Signal Layer 1 w4.2: -8.237,-0.462 ccw(c0,0) -2.576,7.838
  Signal Layer 2 w0.505: -18.02,2.5 -17.7,2.5
  Signal Layer 2 w0.637: -10.41,-3.09 -9.4,-3.67 ; -9.817,-2.065 cw(c0,0) -9.298,-3.766 ; -9.7,-2.14 -8.741,-2.743 ; -9.063,-1.19 cw(c0,0) -8.69,-2.837 ; -9.01,-1.25 -8.02,-2.03 ; -8.238,-0.441 cw(c0,0) -7.952,-2.196 ; -8.18,-0.49 -7.27,-1.27 ; -7.35,0.37 cw(c0,0) -7.216,-1.441 ; -7.32,0.3 -6.47,-0.68 ; -6.423,-0.758 ccw(c0,0) v9@-6.395,0.966
  Signal Layer 2 w1: -17.698,6.188 -17.157,6.194 v1(-16.55,6.2)
  Signal Layer 3 w0.58: v8@-11.263,3.44 v8(-11.97,3.44) v8@-11.246,3.457 ; v8(-11.22,3.44) ccw(c-11.22,3.995) -10.828,3.602 -10.3,4.13 -9.51,5.41 ; -9.394,5.496 cw(c-7.96,4.062) -7.96,6.09
  Signal Layer 3 w0.637: -9.016,4.399 ccw(c0,0) -7.952,6.116 ; -8.98,4.49 -7.62,5.17 ; -8.417,3.565 ccw(c0,0) -7.494,5.235 ; -8.39,3.65 -7.1,4.3 ; -7.734,2.872 ccw(c0,0) -7.014,4.344 ; -7.68,2.94 -6.53,3.48 ; -7.062,2.069 ccw(c0,0) -6.447,3.549 ; -7.02,2.18 -5.89,2.77 ; v9@-6.277,1.561 ccw(c0,0) -5.791,2.881
  Signal Layer 4 w1: C9.1@-25.35,4.27 -25.35,-5.75 -21.135,-9.965 ; -21.03,-9.86 -14.06,-9.86 -14.04,-9.86 -13.95,-9.77 v1(-13.54,-9.77) ; -20.73,-10.37 -14.07,-10.37 v1(-14.06,-10.36) -14.04,-10.36 -14.03,-10.35 v1(-13.54,-10.35) ; v8(-11.97,3.44) -11.95,3.46 v8@-11.22,3.46
  Signal Layer 4 w4.2: -8.248,-0.159 ccw(c0,0) -4.919,6.623
  Bottom Layer w1: v1@-17.95,5.78 -17.95,6.44 v1(-17.91,6.48) -17.17,6.48 v1(-17.16,6.49) -16.83,6.82 R1.2@-16.83,9.224
  other v1: -13.13,-10.05 -14.06,-9.78
  other v8: -11.96,4.81 -11.17,4.81
  other v9: -6.41,1.04 -6.33,1.52
VO_ACDC: C4.1 C6.1 C13.2 C17.2 C18.1 C49.1 EC6.1 EC7.1 pad.10@14.86,5.87 Q1.5 Q1.6 Q1.7 Q1.8 Q1.9 Q2.5 Q2.6 Q2.7 Q2.8 Q2.9@17.67,-6.228 R9.1 R10.2 R11.2 R32.1 | length 37.6
  Top Layer w0.2: R10.2@10.062,-21.832 10.062,-22.444 C18.1@10.12,-22.502
  Top Layer w0.254: R10.2@10.01,-21.64 10.075,-21.575 10.075,-17.975 v3(11.41,-16.64)
  Top Layer w0.3: C13.2@16.04,3.85 C13.2@16.04,4.05
  Top Layer w0.6: pad.10@14.86,5.87 14.86,5.62 15.89,4.59 15.89,3.92 C13.2@16.01,3.8
  Signal Layer 1 w0.254: v3(11.41,-16.64) 12.05,-16 12.05,-7.81 15.787,-4.073 16.367,-4.073 16.4,-4.04 EC7.1@16.4,-3.74
  Signal Layer 1 w0.3: 20.87,-2.54 22.73,-2.54 23.87,-3.68 23.87,-12.22 v3(23.55,-12.54)
  Bottom Layer w0.2: C17.2@11.208,-17.062 11.208,-17.044 C17.2@11.413,-16.84
  Bottom Layer w0.3: R11.2@9.73,-18.11 9.735,-18.11 R11.2@10.06,-17.785
  other v2: 19.705,-6.799 20.405,-6.799 21.105,-6.799 21.805,-6.799 22.505,-6.799 23.205,-6.799 22.155,-6.099 22.855,-6.099 23.205,-5.399 19.005,4.401 19.705,4.401 20.405,4.401 21.105,4.401 21.805,4.401 22.505,4.401 23.205,4.401 18.655,5.101 19.355,5.101 20.055,5.101 20.755,5.101 21.455,5.101 22.155,5.101 22.855,5.101 19.005,5.801 19.705,5.801 20.405,5.801 21.105,5.801 21.805,5.801 22.505,5.801 23.205,5.801 20.055,6.501 20.755,6.501 21.455,6.501 22.155,6.501 22.855,6.501 20.405,7.201 21.105,7.201 21.805,7.201 22.505,7.201 23.205,7.201 20.755,7.901 21.455,7.901 22.155,7.901 22.855,7.901 21.105,8.601 21.805,8.601 22.505,8.601 23.205,8.601 20.755,9.301 21.455,9.301 22.155,9.301 22.855,9.301 21.105,10.001 21.805,10.001 22.505,10.001 23.205,10.001 20.755,10.701 21.455,10.701 22.155,10.701 22.855,10.701 21.105,11.401 21.805,11.401 22.505,11.401 23.205,11.401
  other v4: 17.67,-5.338
  other v6: 17.67,-7.09 16.695,-6.652 18.645,-6.652 17.67,-6.214 16.695,-5.776 18.645,-5.776
VOUT_C: C38.1 D13.1 J4.A4 J4.A9 J4.B4 J4.B9 Q2.1 Q2.2 Q2.3 R35.2 R36.2 | length 8.7
  Top Layer w0.2: J4.A4@16.56,-22.32 16.55,-22.33 15.737,-22.33 15.59,-22.183 15.59,-19.98 15.74,-19.83 J4.A9@16.81,-19.83 17.51,-19.83 17.74,-20.06 J4.B4@18.23,-20.06 ; J4.A4@16.81,-22.33 17.53,-22.33 17.78,-22.58 J4.B9@18.41,-22.58 ; v1@17.45,-8.8 v1@17.77,-8.8 ; v1@18.362,-8.789 18.659,-8.789 v1@18.66,-8.79 ; J4.B9@18.61,-22.55 J4.B9@18.64,-22.58 ; v1@18.665,-8.789 18.959,-8.789 v1@18.97,-8.8
  other v1: 22.53,-8.99 23.16,-8.99 20.18,-8.98 21,-8.98 21.74,-8.98 17.62,-8.94 18.43,-8.94 19.29,-8.94 19.71,-8.94 18.04,-8.93 18.86,-8.93 17.64,-8.57 18.06,-8.56 18.45,-8.57 18.88,-8.56 19.31,-8.57 19.73,-8.57 17.65,-8.23 18.07,-8.22 18.46,-8.23 18.89,-8.22 19.32,-8.23 19.74,-8.23 20.23,-8.22 21.01,-8.19 21.77,-8.17 22.53,-8.19 23.17,-8.19
VSR_SW: C5.2 C31.2 pad.9@10.01,-4.04 pad.10@11.58,5.85 Q1.1 Q1.2 Q1.3 R34.1 R50.1 U5.2 | length 179.8
  Top Layer w0.254: 8.178,-6.615 cw(c0,0) 8.223,6.56 ; 8.187,-6.594 8.195,-6.602 8.928,-6.602 9.536,-7.21 v7(10.3,-7.21) ; C5.2@10.66,9.092 10.66,9.28 11.07,9.69 v1(11.07,10.13)
  Top Layer w0.4: R50.1@11.52,4.24 11.455,4.305 11.455,5.725 pad.10@11.58,5.85
  Top Layer w4.284: 5.726,-5.542 cw(c-0.027,0.012) 7.936,0.737
  Signal Layer 3 w0.254: v7@10.39,-7.12 ccw(c9.207,-5.937) 10.88,-5.937 10.88,-5.25 cw(c12.98,-5.25) 11.495,-3.765 12.75,-2.51 ccw(c12.05,-1.81) 13.04,-1.81 13.04,2.65 ccw(c12.42,2.65) 12.42,3.27 11.37,3.8 10.704,4.466 cw(c11.438,5.2) 10.4,5.2 10.4,8.88 11.07,9.55 v1(11.07,10.13)
  Bottom Layer w0.4: 10.4,6.33 ccw(c10.4,6.48) 10.55,6.48 10.55,8.31 11.82,9.58 R34.1@13.41,9.58 ; v1(11.07,10.13) 11.11,10.17 11.11,10.51 12.47,11.87 15.814,11.87
  Bottom Layer w0.5: R34.1@13.606,9.592 13.859,9.592 13.883,9.616 14.726,9.616 14.92,9.81 15.75,9.81 15.98,10.04 v1(16.01,10.04) v1@16.01,10.811 ; 15.91,11.35 15.994,11.266 15.994,10.876 v1@16.01,10.86
  Bottom Layer w4.284: 5.749,5.546 ccw(c-0.027,0.012) 7.964,0.387
  other v1: 16.025,9.211 18.78,10.72 16.015,10.911
  other v5: 11.5,-1.29 12.23,-1.1 11.61,-0.34 12.32,-0.34 12.32,0.49 11.61,0.5 11.52,1.42 12.25,1.42 12.15,2.18 11.34,2.21
VSW: D3.2 U8.2 | length 13.1
  Top Layer w1: v1(-19.15,2.4) D3.2@-19.03,2.4 ; D3.2@-19,2.81 v1(-18.59,2.4) ; D3.2@-19,3.31 -19,3.024 D3.2@-18.763,2.787 ; D3.2@-18.483,2.507 -18.436,2.46 -18,2.46 v1(-17.93,2.39)
  Signal Layer 1 w0.6: v1(-19.15,2.4) v1(-18.59,2.4) -18.588,2.398 -17.941,2.398 -17.933,2.39 v1(-17.93,2.39)
  Signal Layer 2 w0.6: v1(-19.15,2.4) v1(-18.59,2.4) -18.588,2.398 -17.941,2.398 -17.933,2.39 v1(-17.93,2.39)
  Signal Layer 2 w0.637: v1@-17.89,2.43 -13.14,2.43
  Signal Layer 3 w0.6: v1(-19.15,2.4) v1(-18.59,2.4) -18.588,2.398 -17.941,2.398 -17.933,2.39 v1(-17.93,2.39)
  Signal Layer 4 w0.6: v1(-19.15,2.4) v1(-18.59,2.4) -18.588,2.398 -17.941,2.398 -17.933,2.39 v1(-17.93,2.39)
  Bottom Layer w0.5: U8.2@-19.05,2.02 -19.129,2.099 -19.129,2.379 v1(-19.15,2.4) v1(-18.59,2.4) -18.59,2.37 -18.37,2.15 U8.2@-18.37,1.99
WCC1: C27.2 R25.1 U1.17 | length 15.2
  Top Layer w0.2: v3(20.96,-9.75) 21.69,-9.75 C27.2@21.91,-9.97
  Signal Layer 1 w0.2: v3@20.188,-22.062 20.79,-21.46 20.79,-16.48 22.03,-15.24 22.03,-10.82 v3(20.96,-9.75)
  Bottom Layer w0.2: U1.17@20.864,-10.324 20.872,-10.317 20.872,-9.865 20.96,-9.777 v3(20.96,-9.75)
  other v3: 20.15,-22.09
WCC2: C30.2 R28.1 U1.14 | length 11.9
  Top Layer w0.2: C30.2@18.85,-9.94 18.85,-9.919 18.97,-9.799 19.251,-9.799 v3(19.27,-9.78) v3@19.243,-9.78
  Signal Layer 1 w0.2: v3(19.27,-9.78) 19.289,-9.799 19.289,-9.929 19.96,-10.6 21.05,-10.6 21.47,-11.02 21.47,-15.15 20.27,-16.35 20.27,-18.639 20.259,-18.65 20.259,-18.721 v3(20.24,-18.74)
  Bottom Layer w0.2: v3(19.27,-9.78) 19.27,-9.807 19.357,-9.894 U1.14@19.357,-10.077 ; U1.14@19.357,-10.317 U1.14@19.364,-10.324
pads on no net: J4.A2 J4.A3 J4.A8 J4.A10 J4.A11 J4.ALIGN1 J4.ALIGN2 J4.B2 J4.B3 J4.B8 J4.B10 J4.B11 Q2.9@16.695,-5.703 Q2.9@17.008,-6.214 Q2.9@17.008,-7.09 Q2.9@17.67,-6.551 Q2.9@17.345,-5.703 Q2.9@17.995,-5.703 Q2.9@18.332,-6.214 Q2.9@18.333,-7.09 Q2.9@18.645,-5.703 U1.4 U1.6 U1.7 U1.12 U1.13 U1.20 U1.21
copper on no net: | length 75.5
  Top Layer w0.254: 8.213,6.574 9.084,6.574 v7(9.74,7.23) 9.671,7.23 v7@9.541,7.1
  Signal Layer 1 w0.254: v7@9.71,7.2 v7(9.74,7.23)
  Signal Layer 2 w0.254: v7@9.75,7.24 9.75,6.632 ccw(c12.29,6.632) 10.494,4.836 11.12,4.21 ; v7@9.78,-6.57 10.719,-5.631 ccw(c9.968,-4.88) 11.03,-4.88 cw(c12.648,-4.88) 11.504,-3.736 12.68,-2.56 ccw(c11.594,-1.474) 13.13,-1.474 13.13,-0.28 13.13,2.468 ccw(c12.208,2.468) 12.86,3.12 12.243,3.737 11.14,4.21
  Bottom Layer w0.254: 7.83,7.024 ccw(c0,0) 8.203,-6.584 ; 7.844,6.965 8.704,6.965 9.713,7.973 ; 8.204,-6.58 v7(9.77,-6.58) ; 9.71,7.979 9.71,9.64 9.75,9.68

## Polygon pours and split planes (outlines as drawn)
VO_ACDC on Bottom Layer "BOTTOM_LAYER_VO_ACDC_P434" (solid, pour order 434): 19.89,12.37 19.89,7.41 23.93,7.41 23.93,12.37
APGND on Bottom Layer "BOTTOM_LAYER_APGND_P239" (solid, remove dead copper, pour order 239): -15.44,-0.01 -15.44,-2.3 -15.38,-2.36 -14.79,-2.36 -14.71,-2.44 -14.71,-4.15 -14.99,-4.43 -15.37,-4.43 -17.99,-4.43 -18.2,-4.22 -18.2,-3.29 -18.25,-3.24 -18.56,-3.24 -18.56,-4.86 -18.98,-5.28 -18.98,-5.61 -18.95,-5.64 -18.17,-5.64 -17.92,-5.39 -15.12,-5.39 -14.15,-4.42 -14.15,-2.25 -14.71,-1.69 -14.71,-0.18 -14.89,0
RTN on Bottom Layer "BOTTOM_LAYER_RTN_P424" (solid, remove dead copper, pour order 424): 12.94,-11.85 12.94,-16.43 16.47,-16.43 15.69,-15.65 15.69,-12.19 15.31,-11.81 12.95,-11.81
RTN on Bottom Layer "BOTTOM_LAYER_RTN_P423" (solid, remove dead copper, pour order 423): 12.94,-16.06 24.09,-16.06 24.09,-24.25 12.94,-24.25
RTN on Bottom Layer "BOTTOM_LAYER_RTN_P421" (solid, remove dead copper, pour order 421): 12.92,-25.58 13.756,-26.416 24.05,-26.416 24.05,-22.87 12.92,-22.87
SGND on Bottom Layer "BOTTOM_LAYER_SGND_P419" (solid, remove dead copper, pour order 419): 18.24,-10.4 24.39,-10.4 24.39,-15.89 16.2,-15.89 16.2,-12.44
VOUT_C on Bottom Layer "BOTTOM_LAYER_VOUT_C_P386" (solid, remove dead copper, pour order 386): 17.14,-7.8 17.14,-9.39 23.87,-9.39 23.87,-7.79 23.72,-7.79 17.13,-7.79
VSR_SW on Bottom Layer "BOTTOM_LAYER_VSR_SW_P380" (solid, remove dead copper, pour order 380): 11.02,1.58 12.71,1.58 12.72,1.59 12.72,-1.9 10.822,-1.9 9.95,-2.51 9.43,-3.65 8.57,-3.03 8.57,1.6
VSR_SW on Bottom Layer "BOTTOM_LAYER_VSR_SW_P354" (solid, remove dead copper, pour order 354): 5.136,2.62 12.72,2.62 12.72,0.11 5.93,0.11 5.67,0.59
VSR_SW on Bottom Layer "BOTTOM_LAYER_VSR_SW_P353" (solid, remove dead copper, pour order 353): 4.99,3.1 12.47,3.1 12.47,6.601 7.667,6.601 6.428,7.84 3.8,7.84 3.26,7.3 3.26,4.83
PGND on Bottom Layer "BOTTOM_LAYER_PGND_P257" (solid, remove dead copper, pour order 257): -26.04,-17.73 -13.96,-17.73 -13.96,-1.8 -16.327,0.567 -18.565,0.565 -18.615,12.29 -26.04,12.29
VSR_SW on Bottom Layer "BOTTOM_LAYER_VSR_SW_P254" (solid, remove dead copper, pour order 254): 13.63,12.3 19.22,12.3 19.22,9.66 17.355,9.667 17.325,7.891 13.63,7.91
Vbus on Bottom Layer "BOTTOM_LAYER_VBUS_P352" (solid, remove dead copper, pour order 352): -17.56,9.82 -17.56,7.96 -18.63,7.96 -18.63,4.19 -18.48,4.04 -17,4.04 -16.01,5.03 -16.01,9.72 -16.11,9.82
NetC7_2 on Bottom Layer "BOTTOM_LAYER_NETC7_2_P281" (solid, remove dead copper, pour order 281): -14.84,-22.828 -14.84,-25.577 -14.121,-26.296 -6.606,-26.296 -5.97,-25.66 -5.97,-23.56 -6.844,-22.686 -14.661,-22.686
NetC7_1 on Bottom Layer "BOTTOM_LAYER_NETC7_1_P280" (solid, remove dead copper, pour order 280): -14.77,-17.796 -14.77,-20.532 -14.045,-21.258 -6.945,-21.258 -6.34,-20.653 -6.34,-18.612 -7.305,-17.648 -14.585,-17.648
NetC2_1 on Bottom Layer "BOTTOM_LAYER_NETC2_1_P279" (solid, remove dead copper, pour order 279): -25.749,-22.618 -25.749,-25.598 -25.159,-26.188 -18.059,-26.188 -17.679,-25.808 -17.679,-23.318 -18.419,-22.578 -25.699,-22.578
PGND on Bottom Layer "BOTTOM_LAYER_PGND_P278" (solid, remove dead copper, pour order 278): -25.75,-17.46 -25.75,-20.44 -25.16,-21.03 -18.06,-21.03 -17.68,-20.65 -17.68,-18.46 -18.72,-17.42 -25.7,-17.42
VSW on Bottom Layer "BOTTOM_LAYER_VSW_P277" (solid, remove dead copper, pour order 277): -19.464,2.78 -17.31,2.78 -17.31,1.87 -19.5,1.87 -19.66,2.03 -19.66,2.666
SGND on Bottom Layer "BOTTOM_LAYER_SGND_P270" (solid, remove dead copper, pour order 270): 13.07,2.64 13.07,-10.24 15.51,-10.24 15.51,2.64
VO_ACDC on Bottom Layer "BOTTOM_LAYER_VO_ACDC_P255" (solid, remove dead copper, pour order 255): 15.75,7.7 15.75,-7.5 23.91,-7.5 23.91,7.7
VOUT_C on Bottom Layer "BOTTOM_LAYER_NONET_P251" (solid, remove dead copper, shelved, pour order 251): -32.118,-85.455 -30.673,-84.01 -30.673,-83.945 -30.396,-83.945 -30.206,-84.135 -30.206,-85.681 -31.134,-85.681 -31.421,-85.967
no net on Bottom Layer "BOTTOM_LAYER_NONET_P242" (solid, remove dead copper, shelved, pour order 242): 4.007,-86.136 4.007,-81.666 4.073,-81.599 6.311,-81.599 6.407,-81.694 6.407,-83.061 7.148,-83.061 7.191,-83.104 7.191,-86.193 4.022,-86.193 4.022,-81.629 4.6,-81.629 4.614,-81.615 4.036,-81.615 4.036,-83.093 7.163,-86.221
no net on Top Layer "Default Coverlay 2 Top" (split plane): -37.134,-75.136 -36.118,-75.136 -36.118,-112.386 -37.117,-112.386
VO_ACDC on Signal Layer 3 "SIGNAL_LAYER_3_VO_ACDC_P438" (solid, pour order 438): 19.89,12.44 19.89,7.48 23.93,7.48 23.93,12.44
VSR_SW on Signal Layer 3 "SIGNAL_LAYER_3_VSR_SW_P433" (solid, remove dead copper, pour order 433): 14.16,12.3 19.19,12.3 19.19,9.66 17.325,9.667 17.304,8.422 14.16,8.438
RTN on Signal Layer 3 "SIGNAL_LAYER_3_RTN_P410" (solid, remove dead copper, pour order 410): 16.2,-16.07 24.07,-16.07 24.1,-16.04 24.1,-24.3 19.67,-24.3 19.67,-19.01 19.41,-18.75 16.47,-18.75 16.15,-18.43 16.15,-16.11
VO_ACDC on Signal Layer 3 "SIGNAL_LAYER_3_VO_ACDC_P409" (solid, remove dead copper, pour order 409): 13.93,7.67 13.93,3.43 14.22,3.14 16.12,3.14 16.12,7.67
SGND on Signal Layer 3 "SIGNAL_LAYER_3_SGND_P408" (solid, remove dead copper, pour order 408): 17.36,-10.42 24.35,-10.42 24.35,-15.91 16.18,-15.91 16.18,-11.5 17.26,-10.42
VOUT_C on Signal Layer 3 "SIGNAL_LAYER_3_VOUT_C_P407" (solid, remove dead copper, pour order 407): 12.9,-22.73 19.58,-22.73 19.58,-19.19 19.27,-18.88 16.13,-18.88 15.8,-18.55 15.8,-10.58 16.93,-9.45 23.86,-9.45 23.86,-7.8 12.9,-7.8
RTN on Signal Layer 3 "SIGNAL_LAYER_3_RTN_P406" (solid, remove dead copper, pour order 406): 12.93,-25.63 13.766,-26.466 24.06,-26.466 24.06,-23.74 15.63,-23.74 15.3,-23.41 15.3,-22.92 12.93,-22.92
SGND on Signal Layer 3 "SIGNAL_LAYER_3_SGND_P405" (solid, remove dead copper, pour order 405): 13.379,2.7 13.379,-2.001 10.961,-2.001 10.984,-7.46 15.239,-7.46 15.239,2.7
VO_ACDC on Signal Layer 3 "SIGNAL_LAYER_3_VO_ACDC_P404" (solid, remove dead copper, pour order 404): 15.85,7.67 15.85,-7.49 23.882,-7.49 23.882,7.67
VSR_SW on Signal Layer 3 "SIGNAL_LAYER_3_VSR_SW_P368" (solid, remove dead copper, pour order 368): 11.05,2.6 11.05,2 11.18,1.87 11.18,-1.46 11.39,-1.67 11.39,-1.69 12.32,-1.69 12.56,-1.45 12.56,-1.2 12.65,-1.11 12.65,2.28 12.3,2.63 11.08,2.63
NetC2_1 on Signal Layer 3 "SIGNAL_LAYER_3_NETC2_1_P361" (solid, remove dead copper, pour order 361): -14.842,-12.338 -14.842,-13.618 -14.35,-14.11 -12.674,-14.11 -12.182,-13.618 -12.182,-12.598 -12.452,-12.328 -14.822,-12.328
Vbus on Signal Layer 3 "SIGNAL_LAYER_3_VBUS_P360" (solid, remove dead copper, pour order 360): -14.68,-9.31 -14.68,-10.59 -14.4,-10.87 -12.3,-10.87 -12.02,-10.59 -12.02,-9.57 -12.28,-9.31
Vbus on Signal Layer 3 "SIGNAL_LAYER_3_VBUS_P272" (solid, remove dead copper, pour order 272): -18.28,6.74 -18.28,5.8 -17.91,5.43 -16.67,5.43 -16.11,5.99 -16.11,7.03 -18.073,7.03
NetC7_2 on Signal Layer 3 "SIGNAL_LAYER_3_NETC7_2_P345" (solid, remove dead copper, pour order 345): -10.97,-23.45 -10.97,-24.82 -10.64,-25.15 -6.45,-25.15 -6.23,-24.93 -6.23,-23.77 -6.55,-23.45 -10.55,-23.45
NetC7_1 on Signal Layer 3 "SIGNAL_LAYER_3_NETC7_1_P339" (solid, remove dead copper, pour order 339): -11,-18.92 -11,-20.28 -10.66,-20.62 -6.88,-20.62 -6.66,-20.4 -6.66,-18.96 -6.7,-18.92 -10.98,-18.92
PGND on Signal Layer 3 "SIGNAL_LAYER_3_PGND_P294" (solid, remove dead copper, pour order 294): -25.92,12.36 -25.92,-19.29 -14.02,-19.29 -14.02,12.5 -25.84,12.5 -25.84,12.36
no net on Top Layer "Default Coverlay 2 Bottom" (split plane): -37.134,-75.136 -36.118,-75.136 -36.118,-112.386 -37.117,-112.386
VO_ACDC on Signal Layer 4 "SIGNAL_LAYER_4_VO_ACDC_P439" (solid, pour order 439): 19.91,12.42 19.91,7.46 23.95,7.46 23.95,12.42
VSR_SW on Signal Layer 4 "SIGNAL_LAYER_4_VSR_SW_P432" (solid, remove dead copper, pour order 432): 14.17,12.28 19.2,12.28 19.2,9.64 17.335,9.647 17.314,8.422 14.17,8.438
RTN on Signal Layer 4 "SIGNAL_LAYER_4_RTN_P417" (solid, remove dead copper, pour order 417): 16.24,-16.06 24.11,-16.06 24.14,-16.03 24.14,-24.29 19.71,-24.29 19.71,-19 19.45,-18.74 16.51,-18.74 16.19,-18.42 16.19,-16.1
VO_ACDC on Signal Layer 4 "SIGNAL_LAYER_4_VO_ACDC_P416" (solid, remove dead copper, pour order 416): 13.97,7.68 13.97,3.44 14.26,3.15 16.16,3.15 16.16,7.68
SGND on Signal Layer 4 "SIGNAL_LAYER_4_SGND_P415" (solid, remove dead copper, pour order 415): 17.4,-10.41 24.39,-10.41 24.39,-15.9 16.22,-15.9 16.22,-11.49 17.3,-10.41
VOUT_C on Signal Layer 4 "SIGNAL_LAYER_4_VOUT_C_P414" (solid, remove dead copper, pour order 414): 12.94,-22.72 19.62,-22.72 19.62,-19.18 19.31,-18.87 16.17,-18.87 15.84,-18.54 15.84,-10.57 16.97,-9.44 23.9,-9.44 23.9,-7.79 12.94,-7.79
